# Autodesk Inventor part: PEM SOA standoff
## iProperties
Author: John A. Hunter
Shininess: 64.0
Angle Display Precision: 2
Document Length Units: 11272
Document Angle Units: 11286
Document Time Units: 11279
Document Mass Units: 11290
Document Length Units Precision: 3
Document Angle Units Precision: 2
Compacted: True
PropertySet Name: _Private Model Information
Created: 2002-08
Part Number: PEM SOA standoff
Material: Aluminum-6061
Description: SOA-832-4
Document SubType Name: Modeling
Designer: John A. Hunter
Control State: 0
Master: False
Checked Out: False
PropertySet Name: Design Tracking Control
Density: 0.0
Volumn: 0.0
Area: 0.0
PropertySet Name: Model Information
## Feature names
1. Extrusion1
2. Extrusion2
3. Hole1
